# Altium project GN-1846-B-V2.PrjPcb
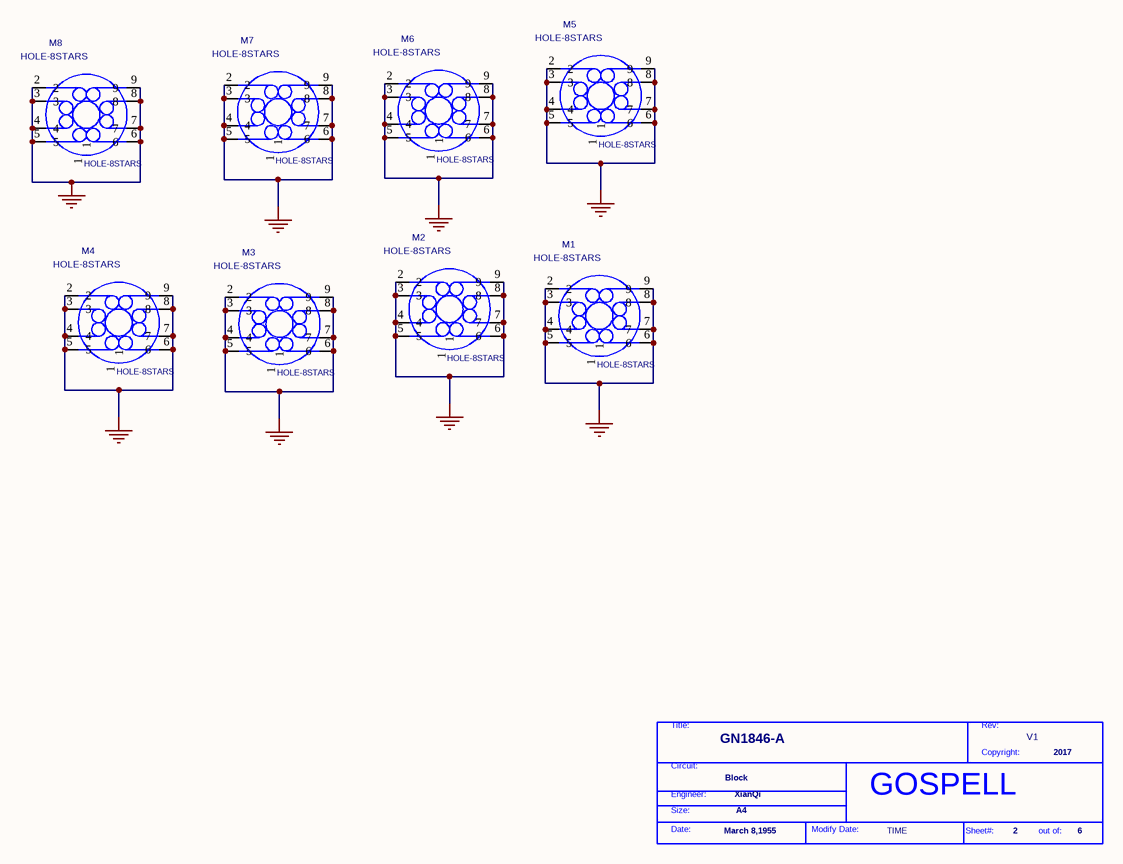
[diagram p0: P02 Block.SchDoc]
6 sheets, 362 parts. Net scope: flat (ports and power ports of the same name join across sheets).
Board file: GN-1846-B-V2.PcbDoc
Sheets:
  P02 Block.SchDoc
  P05 PHY 3.SchDoc
  P06 CONNECT & LED.SchDoc
  P04 PHY 2.SchDoc
  P03 PHY 1.SchDoc
  P01 Note & Title.SchDoc

## Sheet P02 Block.SchDoc
size 297 x 209 mm

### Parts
(Parts that share a designator on the sheet are numbered #1, #2 ... from top to bottom, then left to right.)
*#1  Page Modify Date: TIME  Engineer: XianQi  Copyright: 2017  Title: GN1846-A  RevCode: V1  Page Size: A4  Page Create Date: March 8,1955  Page Number: 2  Page Count: 6  Doc: Block  (hidden comment: GOSPELL)  (graphical)
M1  HOLE-8STARS  [HK]
M2  HOLE-8STARS  [HK]
M3  HOLE-8STARS  [HK]
M4  HOLE-8STARS  [HK]
M5  HOLE-8STARS  [HK]
M6  HOLE-8STARS  [HK]
M7  HOLE-8STARS  [HK]
M8  HOLE-8STARS  [HK]

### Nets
GND: M1.2 M1.3 M1.4 M1.5 M1.6 M1.7 M1.8 M1.9 M2.2 M2.3 M2.4 M2.5 M2.6 M2.7 M2.8 M2.9 M3.2 M3.3 M3.4 M3.5 M3.6 M3.7 M3.8 M3.9 M4.2 M4.3 M4.4 M4.5 M4.6 M4.7 M4.8 M4.9 M5.2 M5.3 M5.4 M5.5 M5.6 M5.7 M5.8 M5.9 M6.2 M6.3 M6.4 M6.5 M6.6 M6.7 M6.8 M6.9 M7.2 M7.3 M7.4 M7.5 M7.6 M7.7 M7.8 M7.9 M8.2 M8.3 M8.4 M8.5 M8.6 M8.7 M8.8 M8.9

Not connected (* = marked no-connect by the designer): M1 1; M2 1; M3 1; M4 1; M5 1; M6 1; M7 1; M8 1

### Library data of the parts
M1-M8 = GEN35: Layer: Top

## Sheet P05 PHY 3.SchDoc
size 420 x 297 mm
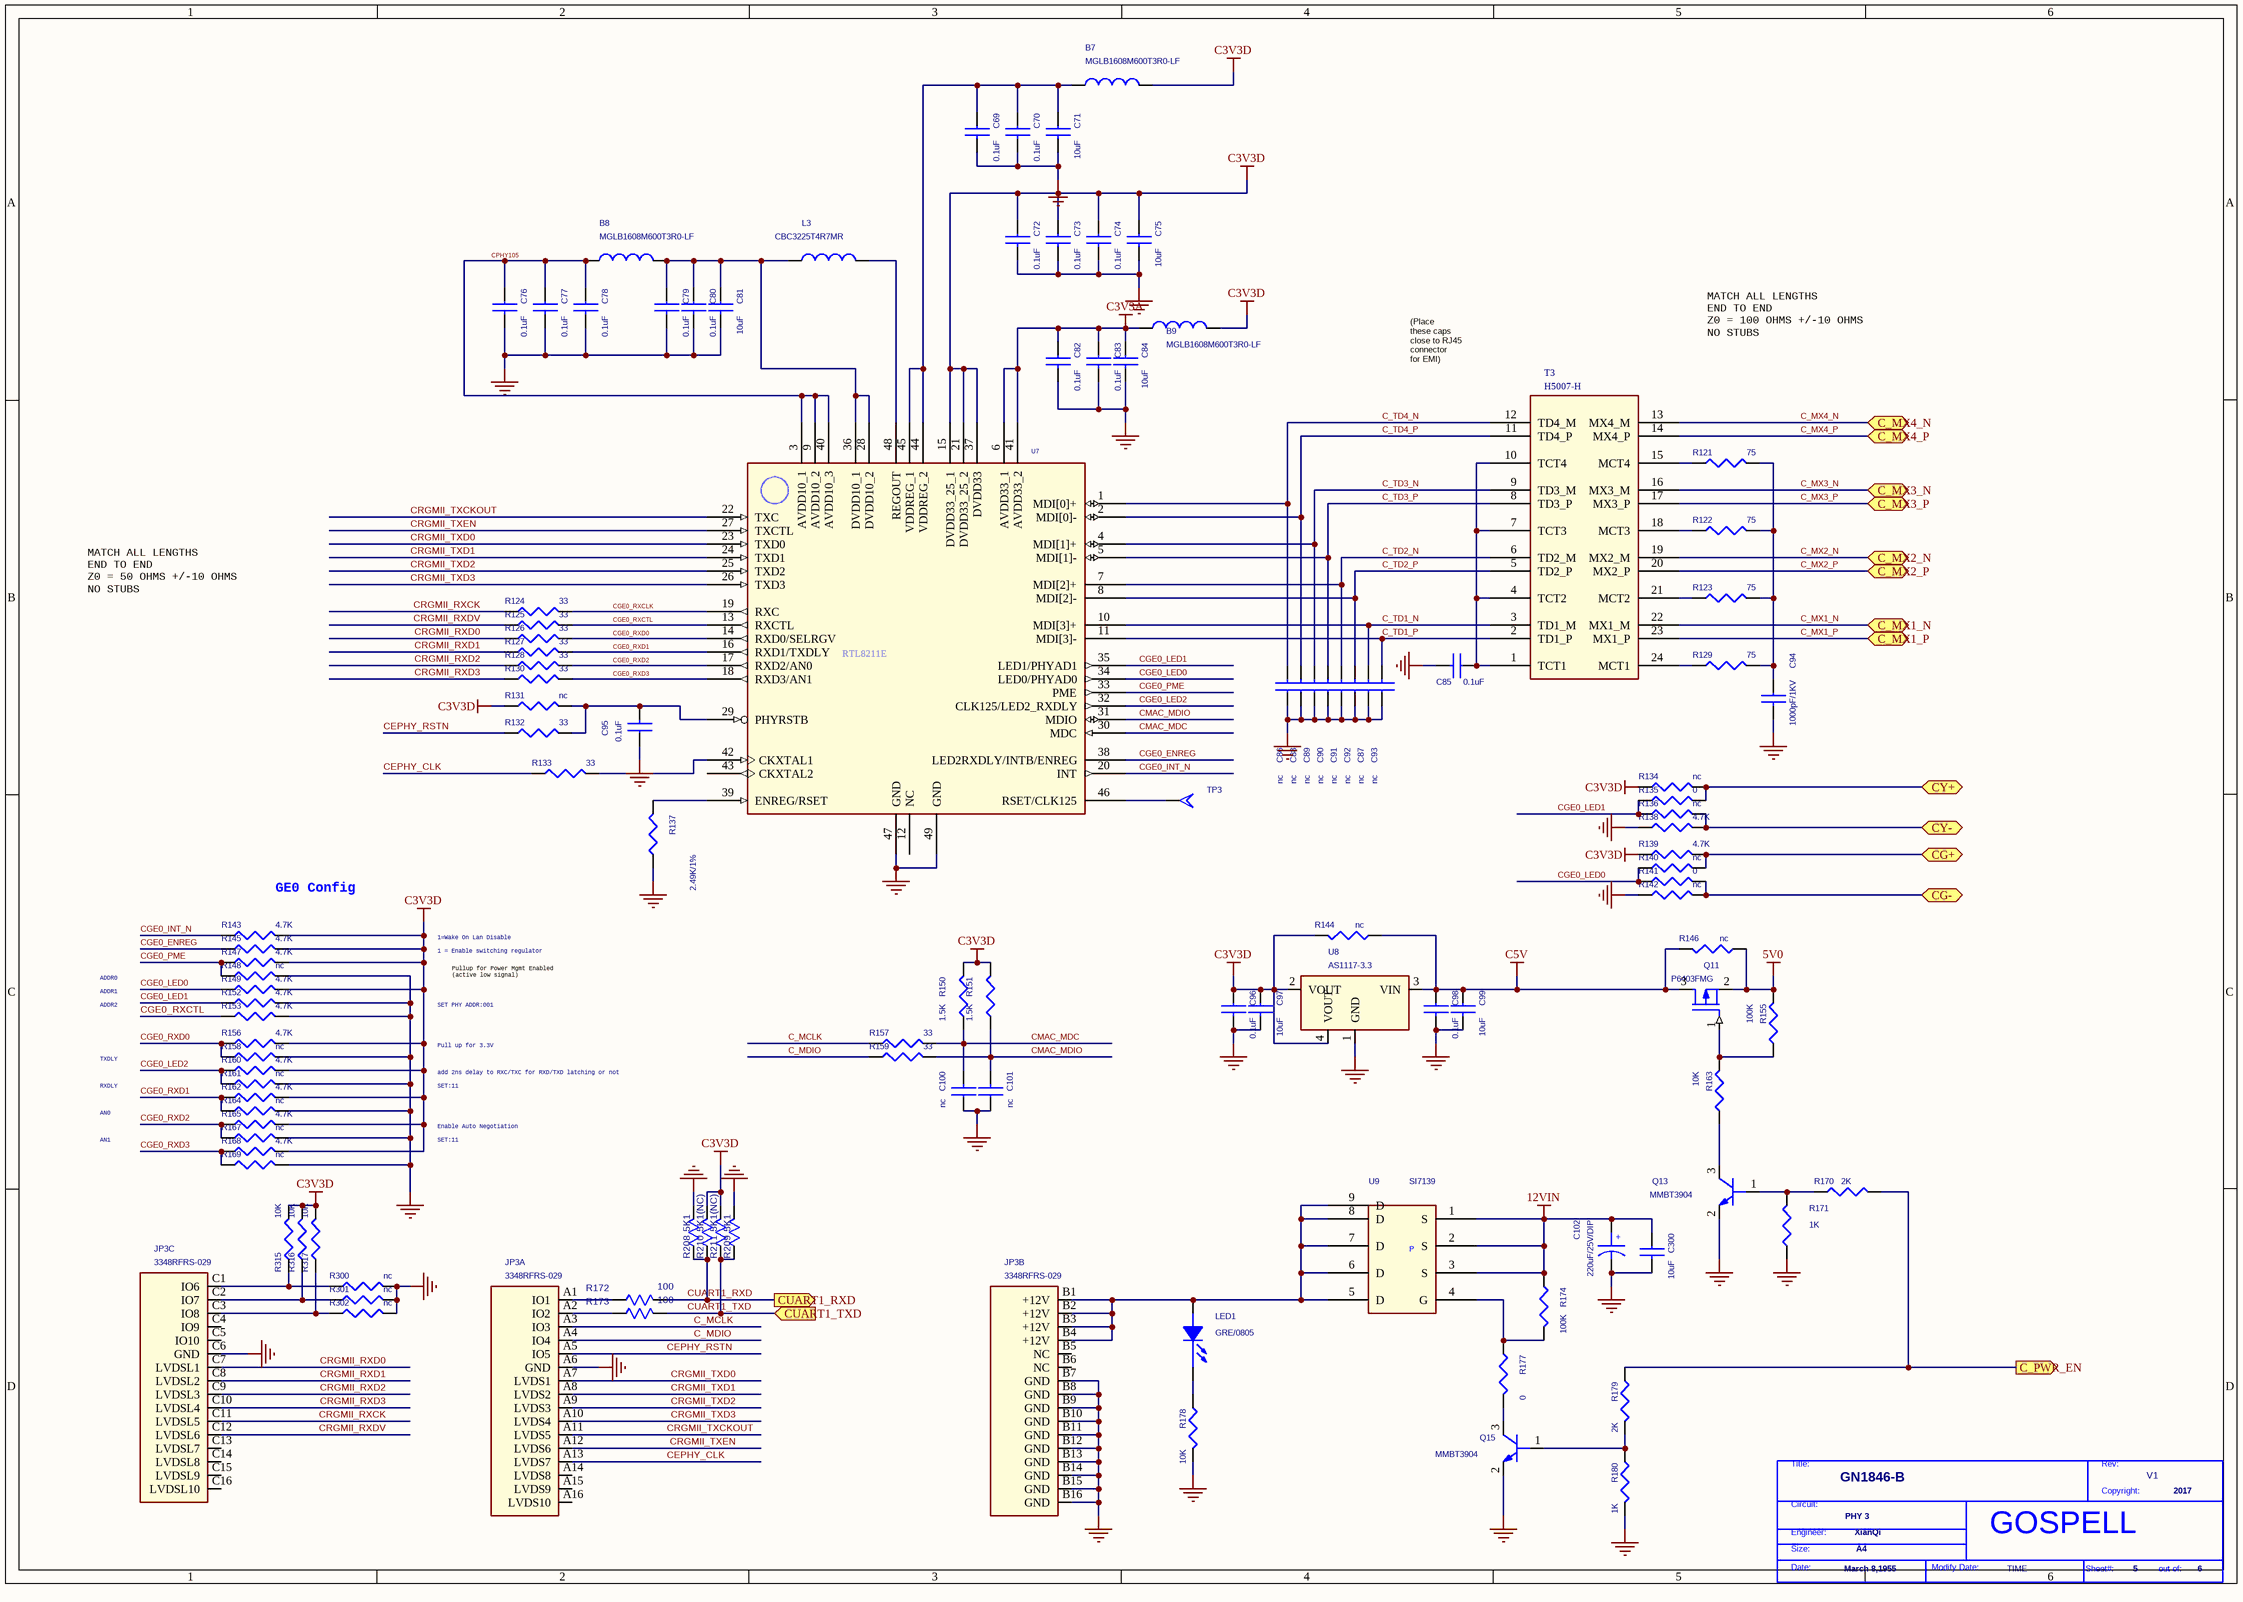
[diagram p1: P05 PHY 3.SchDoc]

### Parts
(Parts that share a designator on the sheet are numbered #1, #2 ... from top to bottom, then left to right.)
*#2  Page Modify Date: TIME  Engineer: XianQi  Copyright: 2017  Title: GN1846-B  RevCode: V1  Page Size: A4  Page Create Date: March 8,1955  Page Number: 5  Page Count: 6  Doc: PHY 3  (hidden comment: GOSPELL)  (graphical)
B7  MGLB1608M600T3R0-LF  [L0603]
B8  MGLB1608M600T3R0-LF  [L0603]
B9  MGLB1608M600T3R0-LF  [L0603]
C69  0.1uF  [0402C]
C70  0.1uF  [0402C]
C71  10uF  [C0603]
C72  0.1uF  [0402C]
C73  0.1uF  [0402C]
C74  0.1uF  [0402C]
C75  10uF  [C0603]
C76  0.1uF  [0402C]
C77  0.1uF  [0402C]
C78  0.1uF  [0402C]
C79  0.1uF  [0402C]
C80  0.1uF  [0402C]
C81  10uF  [C0603]
C82  0.1uF  [0402C]
C83  0.1uF  [0402C]
C84  10uF  [C0603]
C85  0.1uF  [0402C]
C86  nc  [0402C]
C87  nc  [0402C]
C88  nc  [0402C]
C89  nc  [0402C]
C90  nc  [0402C]
C91  nc  [0402C]
C92  nc  [0402C]
C93  nc  [0402C]
C94  1000pF/1KV  [C1206]
C95  0.1uF  [0402C]
C96  0.1uF  [0402C]
C97  10uF  [C0603]
C98  0.1uF  [0402C]
C99  10uF  [C0603]
C100  nc  [0402C]
C101  nc  [0402C]
C102  220uF/25V/DIP  [CE8X3.5]
C300  10uF  [c1206]
JP3  3348RFRS-029  [3348RFRS-029]  (parts A,B,C of 3)
L3  CBC3225T4R7MR  [FB0805]
LED1  GRE/0805  [LED0805]
Q11  P6403FMG  [SOT23]
Q13  MMBT3904  [SOT23]
Q15  MMBT3904  [SOT23]
R121  75  [0402R]
R122  75  [0402R]
R123  75  [0402R]
R124  33  [0402R]
R125  33  [0402R]
R126  33  [0402R]
R127  33  [0402R]
R128  33  [0402R]
R129  75  [0402R]
R130  33  [0402R]
R131  nc  [0402R]
R132  33  [0402R]
R133  33  [0402R]
R134  nc  [0402R]
R135  0  [0402R]
R136  nc  [0402R]
R137  2.49K/1%  [0402R]
R138  4.7K  [0402R]
R139  4.7K  [0402R]
R140  nc  [0402R]
R141  0  [0402R]
R142  nc  [0402R]
R143  4.7K  [0402R]
R144  nc  [R0603]
R145  4.7K  [0402R]
R146  nc  [R0603]
R147  4.7K  [0402R]
R148  nc  [0402R]
R149  4.7K  [0402R]
R150  1.5K  [0402R]
R151  1.5K  [0402R]
R152  4.7K  [0402R]
R153  4.7K  [0402R]
R155  100K  [R0603]
R156  4.7K  [0402R]
R157  33  [0402R]
R158  nc  [0402R]
R159  33  [0402R]
R160  4.7K  [0402R]
R161  nc  [0402R]
R162  4.7K  [0402R]
R163  10K  [0402R]
R164  nc  [0402R]
R165  4.7K  [0402R]
R167  nc  [0402R]
R168  4.7K  [0402R]
R169  nc  [0402R]
R170  2K  [0402R]
R171  1K  [0402R]
R172  100  [0402R]
R173  100  [0402R]
R174  100K  [R0603]
R177  0  [0402R]
R178  10K  [0402R]
R179  2K  [0402R]
R180  1K  [0402R]
R208  5K1  [0402R]
R209  5K1  [0402R]
R210  5K1(NC)  [0402R]
R211  5K1(NC)  [0402R]
R300  nc  [0402R]
R301  nc  [0402R]
R302  nc  [0402R]
R315  10K  [0402R]
R316  10K  [0402R]
R317  10K  [0402R]
T3  H5007-H  [H5007-H]
TP3  T POINT A  [TP_G]  (value not drawn)
U7  RTL8211D  [QFN-48P-RTL8211]  (value not drawn)
U8  AS1117-3.3  [SOT223]
U9  SI7139  [PowerPAKSO8]

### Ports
C_MX1_N (bidir), C_MX1_P (bidir), C_MX2_N (bidir), C_MX2_P (bidir), C_MX3_N (bidir), C_MX3_P (bidir), C_MX4_N (bidir), C_MX4_P (bidir), C_PWR_EN (out), CG+ (bidir), CG- (bidir), CUART1_RXD (out), CUART1_TXD (in), CY+ (bidir), CY- (bidir)

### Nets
5V0: Q11.2(SOURCE) R146.2 R155.1
12VIN: C102.1 C300.1 R174.2 U9.1(S) U9.2(S) U9.3(S)
C3V3A: B9.1 C82.1 C83.1 C84.1 U7.6(AVDD33_1) U7.41(AVDD33_2)
C3V3D: B7.2 B9.2 C72.1 C73.1 C74.1 C75.1 C96.1 C97.1 R131.1 R134.1 R139.1 R143.2 R144.1 R145.2 R147.2 R149.2 R150.2 R151.2 R156.2 R160.2 R162.2 R165.2 R168.2 R210.2(B) R211.2(B) R315.2 R316.2 R317.2 U7.15(DVDD33_25_1) U7.21(DVDD33_25_2) U7.37(DVDD33) U8.2(VOUT) U8.4(VOUT)
C5V: C98.1 C99.1 Q11.3(DRAIN) R144.2 R146.1 U8.3(VIN)
GND: C69.2 C70.2 C71.2 C72.2 C73.2 C74.2 C75.2 C76.2 C77.2 C78.2 C79.2 C80.2 C81.2 C82.2 C83.2 C84.2 C85.2 C86.1 C87.1 C88.1 C89.1 C90.1 C91.1 C92.1 C93.1 C94.2 C95.1 C96.2 C97.2 C98.2 C99.2 C100.1 C101.1 C102.2 C300.2 JP3.A6(GND) JP3.B7(GND) JP3.B8(GND) JP3.B9(GND) JP3.B10(GND) JP3.B11(GND) JP3.B12(GND) JP3.B13(GND) JP3.B14(GND) JP3.B15(GND) JP3.B16(GND) JP3.C6(GND) Q13.2(EMITTER) Q15.2(EMITTER) R137.1 R138.1 R142.1 R148.2 R152.2 R153.2 R158.2 R161.2 R164.2 R167.2 R169.2 R171.1 R178.1 R180.1 R208.2(B) R209.2(B) R300.2 R301.2 R302.2 U7.47(GND) U7.49(GND) U8.1(GND)
C_MCLK: JP3.A3(IO3) R157.1
C_MDIO: JP3.A4(IO4) R159.1
C_MX1_N: T3.22(MX1_M) ; port C_MX1_N
C_MX1_P: T3.23(MX1_P) ; port C_MX1_P
C_MX2_N: T3.19(MX2_M) ; port C_MX2_N
C_MX2_P: T3.20(MX2_P) ; port C_MX2_P
C_MX3_N: T3.16(MX3_M) ; port C_MX3_N
C_MX3_P: T3.17(MX3_P) ; port C_MX3_P
C_MX4_N: T3.13(MX4_M) ; port C_MX4_N
C_MX4_P: T3.14(MX4_P) ; port C_MX4_P
C_TD1_N: C87.2 T3.3(TD1_M) U7.10(MDI[3]+)
C_TD1_P: C93.2 T3.2(TD1_P) U7.11(MDI[3]-)
C_TD2_N: C91.2 T3.6(TD2_M) U7.7(MDI[2]+)
C_TD2_P: C92.2 T3.5(TD2_P) U7.8(MDI[2]-)
C_TD3_N: C89.2 T3.9(TD3_M) U7.4(MDI[1]+)
C_TD3_P: C90.2 T3.8(TD3_P) U7.5(MDI[1]-)
C_TD4_N: C86.2 T3.12(TD4_M) U7.1(MDI[0]+)
C_TD4_P: C88.2 T3.11(TD4_P) U7.2(MDI[0]-)
CEPHY_CLK: JP3.A13(LVDS7) R133.1
CEPHY_RSTN: JP3.A5(IO5) R132.1
CGE0_ENREG: R145.1 U7.38(LED2RXDLY/INTB/ENREG)
CGE0_INT_N: R143.1 U7.20(INT)
CGE0_LED0: R140.1 R141.1 R149.1 U7.34(LED0/PHYAD0)
CGE0_LED1: R135.1 R136.1 R152.1 U7.35(LED1/PHYAD1)
CGE0_LED2: R160.1 R161.1 U7.32(CLK125/LED2_RXDLY)
CGE0_PME: R147.1 R148.1 U7.33(PME)
CGE0_RXCLK: R124.2 U7.19(RXC)
CGE0_RXCTL: R125.2 R153.1 U7.13(RXCTL)
CGE0_RXD0: R126.2 R156.1 R158.1 U7.14(RXD0/SELRGV)
CGE0_RXD1: R127.2 R162.1 R164.1 U7.16(RXD1/TXDLY)
CGE0_RXD2: R128.2 R165.1 R167.1 U7.17(RXD2/AN0)
CGE0_RXD3: R130.2 R168.1 R169.1 U7.18(RXD3/AN1)
CMAC_MDC: C100.2 R150.1 R157.2 U7.30(MDC)
CMAC_MDIO: C101.2 R151.1 R159.2 U7.31(MDIO)
CPHY105: B8.1 C76.1 C77.1 C78.1 U7.3(AVDD10_1) U7.9(AVDD10_2) U7.40(AVDD10_3)
CRGMII_RXCK: JP3.C11(LVDSL5) R124.1
CRGMII_RXD0: JP3.C7(LVDSL1) R126.1
CRGMII_RXD1: JP3.C8(LVDSL2) R127.1
CRGMII_RXD2: JP3.C9(LVDSL3) R128.1
CRGMII_RXD3: JP3.C10(LVDSL4) R130.1
CRGMII_RXDV: JP3.C12(LVDSL6) R125.1
CRGMII_TXCKOUT: JP3.A11(LVDS5) U7.22(TXC)
CRGMII_TXD0: JP3.A7(LVDS1) U7.23(TXD0)
CRGMII_TXD1: JP3.A8(LVDS2) U7.24(TXD1)
CRGMII_TXD2: JP3.A9(LVDS3) U7.25(TXD2)
CRGMII_TXD3: JP3.A10(LVDS4) U7.26(TXD3)
CRGMII_TXEN: JP3.A12(LVDS6) U7.27(TXCTL)
CUART1_RXD: R172.2(B) R208.1(A) R210.1(A) ; port CUART1_RXD
CUART1_TXD: R173.2(B) R209.1(A) R211.1(A) ; port CUART1_TXD
NetB7_1: B7.1 C69.1 C70.1 C71.1 U7.44(VDDREG_2) U7.45(VDDREG_1)
NetB8_2: B8.2 C79.1 C80.1 C81.1 L3.1 U7.28(DVDD10_2) U7.36(DVDD10_1)
NetC85_1: C85.1 T3.1(TCT1) T3.4(TCT2) T3.7(TCT3) T3.10(TCT4)
NetC94_1: C94.1 R121.2 R122.2 R123.2 R129.2
NetC95_2: C95.2 R131.2 R132.2 U7.29(PHYRSTB)
NetJ3_18: R170.2 R179.2 ; port C_PWR_EN
NetJ4_15: R134.2 R135.2 ; port CY+
NetJ4_16: R136.2 R138.2 ; port CY-
NetJ4_17: R139.2 R140.2 ; port CG+
NetJ4_18: R141.2 R142.2 ; port CG-
NetJP3_A1: JP3.A1(IO1) R172.1(A)
NetJP3_A2: JP3.A2(IO2) R173.1(A)
NetJP3_B1: JP3.B1(+12V) JP3.B2(+12V) JP3.B3(+12V) JP3.B4(+12V) LED1.A(ANODE) U9.5(D) U9.6(D) U9.7(D) U9.8(D) U9.9(D)
NetJP3_C1: JP3.C1(IO6) R300.1 R315.1
NetJP3_C2: JP3.C2(IO7) R301.1 R316.1
NetJP3_C3: JP3.C3(IO8) R302.1 R317.1
NetL3_2: L3.2 U7.48(REGOUT)
NetLED1_K: LED1.K(CATHODE) R178.2
NetQ11_1: Q11.1(GATE) R155.2 R163.1
NetQ13_1: Q13.1(BASE) R170.1 R171.2
NetQ13_3: Q13.3(COLLECTOR) R163.2
NetQ15_1: Q15.1(BASE) R179.1 R180.2
NetQ15_3: Q15.3(COLLECTOR) R177.1
NetR121_1: R121.1 T3.15(MCT4)
NetR122_1: R122.1 T3.18(MCT3)
NetR123_1: R123.1 T3.21(MCT2)
NetR129_1: R129.1 T3.24(MCT1)
NetR133_2: R133.2 U7.42(CKXTAL1)
NetR137_2: R137.2 U7.39(ENREG/RSET)
NetR174_1: R174.1 R177.2 U9.4(G)
NetTP3_1: TP3.1(TP) U7.46(RSET/CLK125)

Not connected (* = marked no-connect by the designer): JP3 A14(LVDS8) A15(LVDS9) A16(LVDS10) B5(NC) B6(NC) C4(IO9) C5(IO10) C13(LVDSL7) C14(LVDSL8) C15(LVDSL9) C16(LVDSL10); U7 12(NC) 43(CKXTAL2)

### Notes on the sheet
- (Place
  these caps
  close to RJ45
  connector
  for EMI)
- MATCH ALL LENGTHS
  END TO END
  Z0 = 100 OHMS +/-10 OHMS
  NO STUBS
- MATCH ALL LENGTHS
  END TO END
  Z0 = 50 OHMS +/-10 OHMS
  NO STUBS
- GE0 Config
- 1=Wake On Lan Disable
- ADDR0
- ADDR1
- 1 = Enable switching regulator
- Pullup for Power Mgmt Enabled
  (active low signal)
- ADDR2
- TXDLY
- SET PHY ADDR:001
- Pull up for 3.3V
- add 2ns delay to RXC/TXC for RXD/TXD latching or not
- AN0
- RXDLY
- Enable Auto Negotiation
- SET:11
- AN1

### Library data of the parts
B7-B9 L3 = CHOKE TORROID_0
C69-C101 C300 = CAP NP
C102 = CAP POL
LED1 = LED_2
Q11 = MOSFET P_0
Q13 Q15 = 2N3904
R121-R143 R145 R147-R153 R156-R162 R164 R165 R167-R169 R174 R177 R179 R180 R300-R302 R315-R317 = R_0
R144 R146 R155 R163 R170 R171 = R
R172 R173 R208-R211 = R_1_Dup1: PARTS: 1; LEVEL: STD; PKG_TYPE: SR0603; DEVICE: RK73H1JTTD7502F; PINSWAP: (A,B); OriginalSymbolOrigin: (10,20); CODE: 7091238; %195%%232%%202%%246%: 片式厚膜电阻器-0.1W-75000OHM-+/-1%-0603; %182%%238%%182%%168%%185%%166%%194%%202%(W): 0.1; %215%%232%%214%%181%%212%%202%%208%%237%%198%%171%%178%%238%: +/-1%; COMPONENT_HIGH_MAX: 0.55MM; %208%%161%%192%%224%%195%%251%%179%%198%: 片式厚膜电阻器
R178 = R_1
T3 = PULSE H5007_0
U7 = RTL8211D_0
U8 = AS1117-X_1

## Sheet P06 CONNECT & LED.SchDoc
size 297 x 209 mm
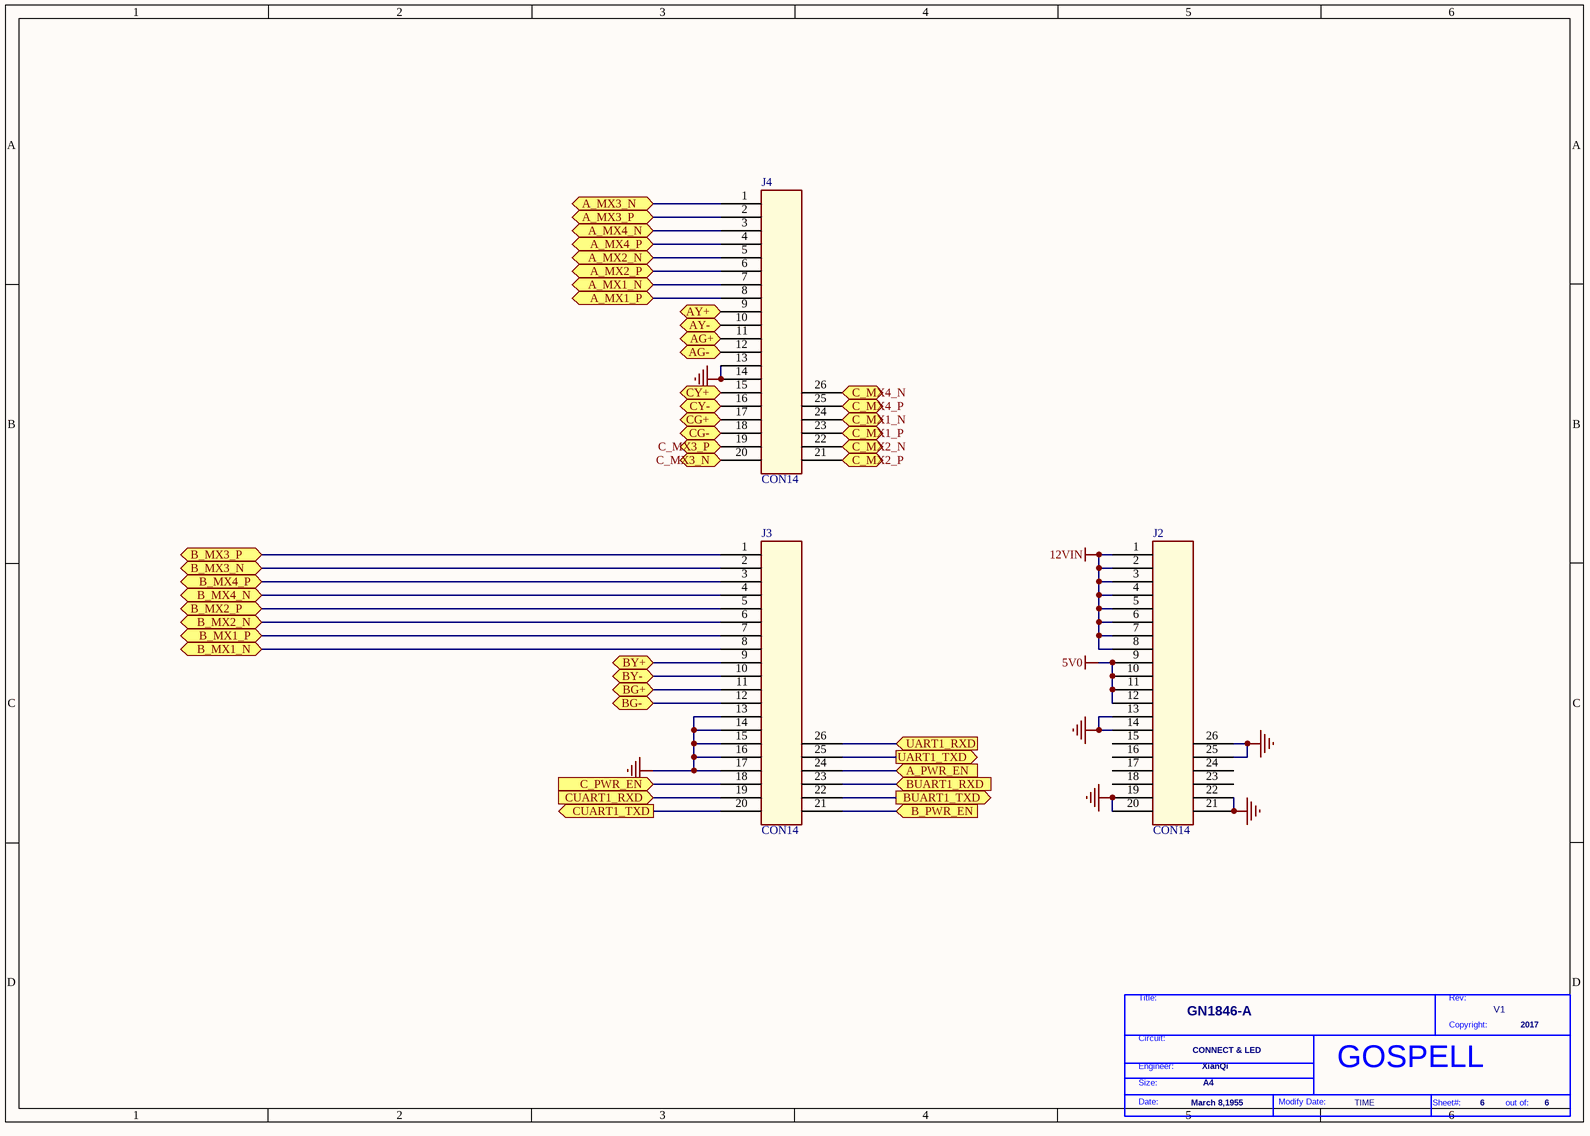
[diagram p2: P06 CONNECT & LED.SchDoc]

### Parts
(Parts that share a designator on the sheet are numbered #1, #2 ... from top to bottom, then left to right.)
*#3  Page Modify Date: TIME  Engineer: XianQi  Copyright: 2017  Title: GN1846-A  RevCode: V1  Page Size: A4  Page Create Date: March 8,1955  Page Number: 6  Doc: CONNECT & LED  (hidden comment: GOSPELL)  (graphical)
J2  CON14  [HERDER13X2-2.0]
J3  CON14  [HERDER13X2-2.0]
J4  CON14  [HERDER13X2-2.0]

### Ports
A_MX1_N (bidir), A_MX1_P (bidir), A_MX2_N (bidir), A_MX2_P (bidir), A_MX3_N (bidir), A_MX3_P (bidir), A_MX4_N (bidir), A_MX4_P (bidir), A_PWR_EN (in), AG+ (bidir), AG- (bidir), AY+ (bidir), AY- (bidir), B_MX1_N (bidir), B_MX1_P (bidir), B_MX2_N (bidir), B_MX2_P (bidir), B_MX3_N (bidir), B_MX3_P (bidir), B_MX4_N (bidir), B_MX4_P (bidir), B_PWR_EN (in), BG+ (bidir), BG- (bidir), BUART1_RXD (in), BUART1_TXD (out), BY+ (bidir), BY- (bidir), C_MX1_N (bidir), C_MX1_P (bidir), C_MX2_N (bidir), C_MX2_P (bidir), C_MX3_N (bidir), C_MX3_P (bidir), C_MX4_N (bidir), C_MX4_P (bidir), C_PWR_EN (in), CG+ (bidir), CG- (bidir), CUART1_RXD (in), CUART1_TXD (out), CY+ (bidir), CY- (bidir), UART1_RXD (in), UART1_TXD (out)

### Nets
5V0: J2.9 J2.10 J2.11 J2.12
12VIN: J2.1 J2.2 J2.3 J2.4 J2.5 J2.6 J2.7 J2.8
GND: J2.13 J2.14 J2.19 J2.20 J2.21 J2.22 J2.25 J2.26 J3.13 J3.14 J3.15 J3.16 J3.17 J4.13 J4.14
A_MX1_N: J4.7 ; port A_MX1_N
A_MX1_P: J4.8 ; port A_MX1_P
A_MX2_N: J4.5 ; port A_MX2_N
A_MX2_P: J4.6 ; port A_MX2_P
A_MX3_N: J4.1 ; port A_MX3_N
A_MX3_P: J4.2 ; port A_MX3_P
A_MX4_N: J4.3 ; port A_MX4_N
A_MX4_P: J4.4 ; port A_MX4_P
B_MX1_N: J3.8 ; port B_MX1_N
B_MX1_P: J3.7 ; port B_MX1_P
B_MX2_N: J3.6 ; port B_MX2_N
B_MX2_P: J3.5 ; port B_MX2_P
B_MX3_N: J3.2 ; port B_MX3_N
B_MX3_P: J3.1 ; port B_MX3_P
B_MX4_N: J3.4 ; port B_MX4_N
B_MX4_P: J3.3 ; port B_MX4_P
BUART1_RXD: J3.23 ; port BUART1_RXD
BUART1_TXD: J3.22 ; port BUART1_TXD
C_MX1_N: J4.24 ; port C_MX1_N
C_MX1_P: J4.23 ; port C_MX1_P
C_MX2_N: J4.22 ; port C_MX2_N
C_MX2_P: J4.21 ; port C_MX2_P
C_MX3_N: J4.20 ; port C_MX3_N
C_MX3_P: J4.19 ; port C_MX3_P
C_MX4_N: J4.26 ; port C_MX4_N
C_MX4_P: J4.25 ; port C_MX4_P
CUART1_RXD: J3.19 ; port CUART1_RXD
CUART1_TXD: J3.20 ; port CUART1_TXD
UART1_RXD: J3.26 ; port UART1_RXD
UART1_TXD: J3.25 ; port UART1_TXD
NetJ3_9: J3.9 ; port BY+
NetJ3_10: J3.10 ; port BY-
NetJ3_11: J3.11 ; port BG+
NetJ3_12: J3.12 ; port BG-
NetJ3_18: J3.18 ; port C_PWR_EN
NetJ3_21: J3.21 ; port B_PWR_EN
NetJ3_24: J3.24 ; port A_PWR_EN
NetJ4_9: J4.9 ; port AY+
NetJ4_10: J4.10 ; port AY-
NetJ4_11: J4.11 ; port AG+
NetJ4_12: J4.12 ; port AG-
NetJ4_15: J4.15 ; port CY+
NetJ4_16: J4.16 ; port CY-
NetJ4_17: J4.17 ; port CG+
NetJ4_18: J4.18 ; port CG-

Not connected (* = marked no-connect by the designer): J2 15(14) 16(14) 17(14) 18(14) 23(14) 24(14)

## Sheet P04 PHY 2.SchDoc
size 420 x 297 mm
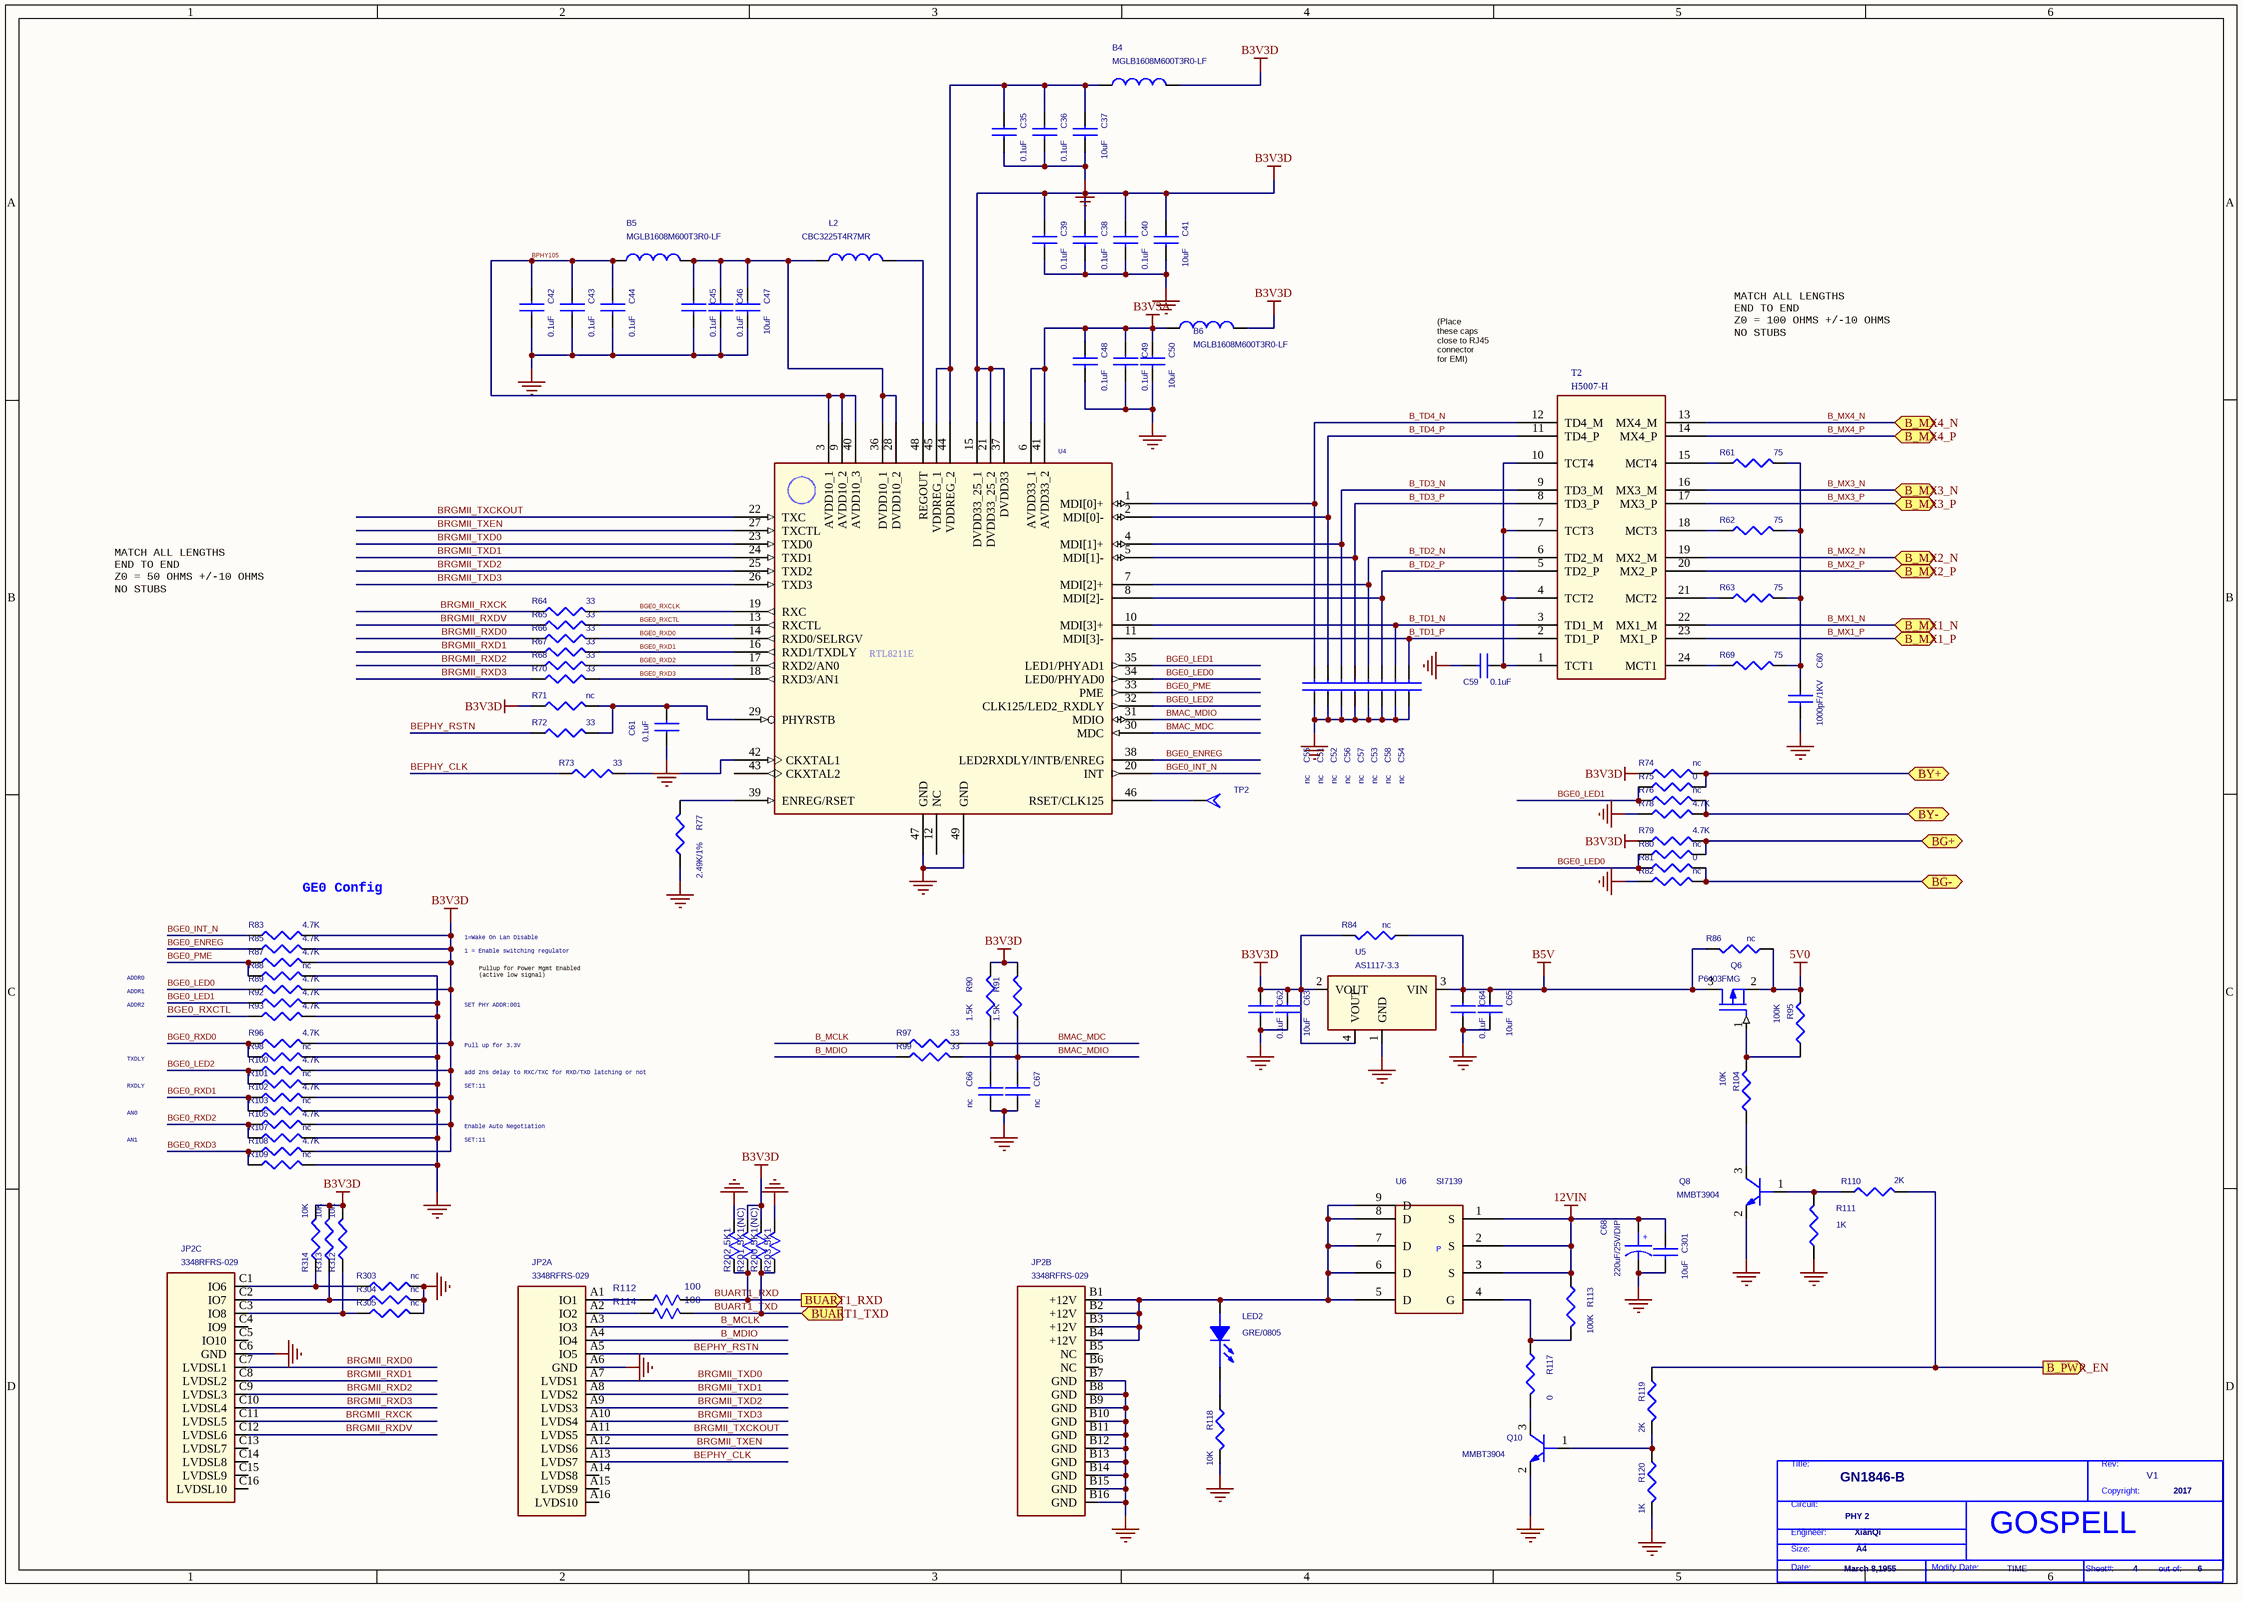
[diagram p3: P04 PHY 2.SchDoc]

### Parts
(Parts that share a designator on the sheet are numbered #1, #2 ... from top to bottom, then left to right.)
*#4  Page Modify Date: TIME  Engineer: XianQi  Copyright: 2017  Title: GN1846-B  RevCode: V1  Page Size: A4  Page Create Date: March 8,1955  Page Number: 4  Page Count: 6  Doc: PHY 2  (hidden comment: GOSPELL)  (graphical)
B4  MGLB1608M600T3R0-LF  [L0603]
B5  MGLB1608M600T3R0-LF  [L0603]
B6  MGLB1608M600T3R0-LF  [L0603]
C35  0.1uF  [0402C]
C36  0.1uF  [0402C]
C37  10uF  [C0603]
C38  0.1uF  [0402C]
C39  0.1uF  [0402C]
C40  0.1uF  [0402C]
C41  10uF  [C0603]
C42  0.1uF  [0402C]
C43  0.1uF  [0402C]
C44  0.1uF  [0402C]
C45  0.1uF  [0402C]
C46  0.1uF  [0402C]
C47  10uF  [C0603]
C48  0.1uF  [0402C]
C49  0.1uF  [0402C]
C50  10uF  [C0603]
C51  nc  [0402C]
C52  nc  [0402C]
C53  nc  [0402C]
C54  nc  [0402C]
C55  nc  [0402C]
C56  nc  [0402C]
C57  nc  [0402C]
C58  nc  [0402C]
C59  0.1uF  [0402C]
C60  1000pF/1KV  [C1206]
C61  0.1uF  [0402C]
C62  0.1uF  [0402C]
C63  10uF  [C0603]
C64  0.1uF  [0402C]
C65  10uF  [C0603]
C66  nc  [0402C]
C67  nc  [0402C]
C68  220uF/25V/DIP  [CE8X3.5]
C301  10uF  [c1206]
JP2  3348RFRS-029  [3348RFRS-029]  (parts A,B,C of 3)
L2  CBC3225T4R7MR  [FB0805]
LED2  GRE/0805  [LED0805]
Q6  P6403FMG  [SOT23]
Q8  MMBT3904  [SOT23]
Q10  MMBT3904  [SOT23]
R61  75  [0402R]
R62  75  [0402R]
R63  75  [0402R]
R64  33  [0402R]
R65  33  [0402R]
R66  33  [0402R]
R67  33  [0402R]
R68  33  [0402R]
R69  75  [0402R]
R70  33  [0402R]
R71  nc  [0402R]
R72  33  [0402R]
R73  33  [0402R]
R74  nc  [0402R]
R75  0  [0402R]
R76  nc  [0402R]
R77  2.49K/1%  [0402R]
R78  4.7K  [0402R]
R79  4.7K  [0402R]
R80  nc  [0402R]
R81  0  [0402R]
R82  nc  [0402R]
R83  4.7K  [0402R]
R84  nc  [R0603]
R85  4.7K  [0402R]
R86  nc  [R0603]
R87  4.7K  [0402R]
R88  nc  [0402R]
R89  4.7K  [0402R]
R90  1.5K  [0402R]
R91  1.5K  [0402R]
R92  4.7K  [0402R]
R93  4.7K  [0402R]
R95  100K  [0402R]
R96  4.7K  [0402R]
R97  33  [0402R]
R98  nc  [0402R]
R99  33  [0402R]
R100  4.7K  [0402R]
R101  nc  [0402R]
R102  4.7K  [0402R]
R103  nc  [0402R]
R104  10K  [0402R]
R105  4.7K  [0402R]
R107  nc  [0402R]
R108  4.7K  [0402R]
R109  nc  [0402R]
R110  2K  [0402R]
R111  1K  [0402R]
R112  100  [0402R]
R113  100K  [R0603]
R114  100  [0402R]
R117  0  [0402R]
R118  10K  [0402R]
R119  2K  [0402R]
R120  1K  [0402R]
R200  5K1(NC)  [0402R]
R201  5K1(NC)  [0402R]
R202  5K1  [0402R]
R203  5K1  [0402R]
R303  nc  [0402R]
R304  nc  [0402R]
R305  nc  [0402R]
R312  10K  [0402R]
R313  10K  [0402R]
R314  10K  [0402R]
T2  H5007-H  [H5007-H]
TP2  T POINT A  [TP_G]  (value not drawn)
U4  RTL8211D  [QFN-48P-RTL8211]  (value not drawn)
U5  AS1117-3.3  [SOT223]
U6  SI7139  [PowerPAKSO8]

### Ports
B_MX1_N (bidir), B_MX1_P (bidir), B_MX2_N (bidir), B_MX2_P (bidir), B_MX3_N (bidir), B_MX3_P (bidir), B_MX4_N (bidir), B_MX4_P (bidir), B_PWR_EN (out), BG+ (bidir), BG- (bidir), BUART1_RXD (out), BUART1_TXD (in), BY+ (bidir), BY- (bidir)

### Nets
5V0: Q6.2(SOURCE) R86.2 R95.1
12VIN: C68.1 C301.1 R113.2 U6.1(S) U6.2(S) U6.3(S)
B3V3A: B6.1 C48.1 C49.1 C50.1 U4.6(AVDD33_1) U4.41(AVDD33_2)
B3V3D: B4.2 B6.2 C38.1 C39.1 C40.1 C41.1 C62.1 C63.1 R71.1 R74.1 R79.1 R83.2 R84.1 R85.2 R87.2 R89.2 R90.2 R91.2 R96.2 R100.2 R102.2 R105.2 R108.2 R200.2(B) R201.2(B) R312.2 R313.2 R314.2 U4.15(DVDD33_25_1) U4.21(DVDD33_25_2) U4.37(DVDD33) U5.2(VOUT) U5.4(VOUT)
B5V: C64.1 C65.1 Q6.3(DRAIN) R84.2 R86.1 U5.3(VIN)
GND: C35.2 C36.2 C37.2 C38.2 C39.2 C40.2 C41.2 C42.2 C43.2 C44.2 C45.2 C46.2 C47.2 C48.2 C49.2 C50.2 C51.1 C52.1 C53.1 C54.1 C55.1 C56.1 C57.1 C58.1 C59.2 C60.2 C61.1 C62.2 C63.2 C64.2 C65.2 C66.1 C67.1 C68.2 C301.2 JP2.A6(GND) JP2.B7(GND) JP2.B8(GND) JP2.B9(GND) JP2.B10(GND) JP2.B11(GND) JP2.B12(GND) JP2.B13(GND) JP2.B14(GND) JP2.B15(GND) JP2.B16(GND) JP2.C6(GND) Q8.2(EMITTER) Q10.2(EMITTER) R77.1 R78.1 R82.1 R88.2 R92.2 R93.2 R98.2 R101.2 R103.2 R107.2 R109.2 R111.1 R118.1 R120.1 R202.2(B) R203.2(B) R303.2 R304.2 R305.2 U4.47(GND) U4.49(GND) U5.1(GND)
B_MCLK: JP2.A3(IO3) R97.1
B_MDIO: JP2.A4(IO4) R99.1
B_MX1_N: T2.22(MX1_M) ; port B_MX1_N
B_MX1_P: T2.23(MX1_P) ; port B_MX1_P
B_MX2_N: T2.19(MX2_M) ; port B_MX2_N
B_MX2_P: T2.20(MX2_P) ; port B_MX2_P
B_MX3_N: T2.16(MX3_M) ; port B_MX3_N
B_MX3_P: T2.17(MX3_P) ; port B_MX3_P
B_MX4_N: T2.13(MX4_M) ; port B_MX4_N
B_MX4_P: T2.14(MX4_P) ; port B_MX4_P
B_TD1_N: C58.2 T2.3(TD1_M) U4.10(MDI[3]+)
B_TD1_P: C54.2 T2.2(TD1_P) U4.11(MDI[3]-)
B_TD2_N: C57.2 T2.6(TD2_M) U4.7(MDI[2]+)
B_TD2_P: C53.2 T2.5(TD2_P) U4.8(MDI[2]-)
B_TD3_N: C52.2 T2.9(TD3_M) U4.4(MDI[1]+)
B_TD3_P: C56.2 T2.8(TD3_P) U4.5(MDI[1]-)
B_TD4_N: C55.2 T2.12(TD4_M) U4.1(MDI[0]+)
B_TD4_P: C51.2 T2.11(TD4_P) U4.2(MDI[0]-)
BEPHY_CLK: JP2.A13(LVDS7) R73.1
BEPHY_RSTN: JP2.A5(IO5) R72.1
BGE0_ENREG: R85.1 U4.38(LED2RXDLY/INTB/ENREG)
BGE0_INT_N: R83.1 U4.20(INT)
BGE0_LED0: R80.1 R81.1 R89.1 U4.34(LED0/PHYAD0)
BGE0_LED1: R75.1 R76.1 R92.1 U4.35(LED1/PHYAD1)
BGE0_LED2: R100.1 R101.1 U4.32(CLK125/LED2_RXDLY)
BGE0_PME: R87.1 R88.1 U4.33(PME)
BGE0_RXCLK: R64.2 U4.19(RXC)
BGE0_RXCTL: R65.2 R93.1 U4.13(RXCTL)
BGE0_RXD0: R66.2 R96.1 R98.1 U4.14(RXD0/SELRGV)
BGE0_RXD1: R67.2 R102.1 R103.1 U4.16(RXD1/TXDLY)
BGE0_RXD2: R68.2 R105.1 R107.1 U4.17(RXD2/AN0)
BGE0_RXD3: R70.2 R108.1 R109.1 U4.18(RXD3/AN1)
BMAC_MDC: C66.2 R90.1 R97.2 U4.30(MDC)
BMAC_MDIO: C67.2 R91.1 R99.2 U4.31(MDIO)
BPHY105: B5.1 C42.1 C43.1 C44.1 U4.3(AVDD10_1) U4.9(AVDD10_2) U4.40(AVDD10_3)
BRGMII_RXCK: JP2.C11(LVDSL5) R64.1
BRGMII_RXD0: JP2.C7(LVDSL1) R66.1
BRGMII_RXD1: JP2.C8(LVDSL2) R67.1
BRGMII_RXD2: JP2.C9(LVDSL3) R68.1
BRGMII_RXD3: JP2.C10(LVDSL4) R70.1
BRGMII_RXDV: JP2.C12(LVDSL6) R65.1
BRGMII_TXCKOUT: JP2.A11(LVDS5) U4.22(TXC)
BRGMII_TXD0: JP2.A7(LVDS1) U4.23(TXD0)
BRGMII_TXD1: JP2.A8(LVDS2) U4.24(TXD1)
BRGMII_TXD2: JP2.A9(LVDS3) U4.25(TXD2)
BRGMII_TXD3: JP2.A10(LVDS4) U4.26(TXD3)
BRGMII_TXEN: JP2.A12(LVDS6) U4.27(TXCTL)
BUART1_RXD: R112.2(B) R201.1(A) R202.1(A) ; port BUART1_RXD
BUART1_TXD: R114.2(B) R200.1(A) R203.1(A) ; port BUART1_TXD
NetB4_1: B4.1 C35.1 C36.1 C37.1 U4.44(VDDREG_2) U4.45(VDDREG_1)
NetB5_2: B5.2 C45.1 C46.1 C47.1 L2.1 U4.28(DVDD10_2) U4.36(DVDD10_1)
NetC59_1: C59.1 T2.1(TCT1) T2.4(TCT2) T2.7(TCT3) T2.10(TCT4)
NetC60_1: C60.1 R61.2 R62.2 R63.2 R69.2
NetC61_2: C61.2 R71.2 R72.2 U4.29(PHYRSTB)
NetJ3_9: R74.2 R75.2 ; port BY+
NetJ3_10: R76.2 R78.2 ; port BY-
NetJ3_11: R79.2 R80.2 ; port BG+
NetJ3_12: R81.2 R82.2 ; port BG-
NetJ3_21: R110.2 R119.2 ; port B_PWR_EN
NetJP2_A1: JP2.A1(IO1) R112.1(A)
NetJP2_A2: JP2.A2(IO2) R114.1(A)
NetJP2_B1: JP2.B1(+12V) JP2.B2(+12V) JP2.B3(+12V) JP2.B4(+12V) LED2.A(ANODE) U6.5(D) U6.6(D) U6.7(D) U6.8(D) U6.9(D)
NetJP2_C1: JP2.C1(IO6) R303.1 R314.1
NetJP2_C2: JP2.C2(IO7) R304.1 R313.1
NetJP2_C3: JP2.C3(IO8) R305.1 R312.1
NetL2_2: L2.2 U4.48(REGOUT)
NetLED2_K: LED2.K(CATHODE) R118.2
NetQ6_1: Q6.1(GATE) R95.2 R104.1
NetQ8_1: Q8.1(BASE) R110.1 R111.2
NetQ8_3: Q8.3(COLLECTOR) R104.2
NetQ10_1: Q10.1(BASE) R119.1 R120.2
NetQ10_3: Q10.3(COLLECTOR) R117.1
NetR61_1: R61.1 T2.15(MCT4)
NetR62_1: R62.1 T2.18(MCT3)
NetR63_1: R63.1 T2.21(MCT2)
NetR69_1: R69.1 T2.24(MCT1)
NetR73_2: R73.2 U4.42(CKXTAL1)
NetR77_2: R77.2 U4.39(ENREG/RSET)
NetR113_1: R113.1 R117.2 U6.4(G)
NetTP2_1: TP2.1(TP) U4.46(RSET/CLK125)

Not connected (* = marked no-connect by the designer): JP2 A14(LVDS8) A15(LVDS9) A16(LVDS10) B5(NC) B6(NC) C4(IO9) C5(IO10) C13(LVDSL7) C14(LVDSL8) C15(LVDSL9) C16(LVDSL10); U4 12(NC) 43(CKXTAL2)

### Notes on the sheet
- (Place
  these caps
  close to RJ45
  connector
  for EMI)
- MATCH ALL LENGTHS
  END TO END
  Z0 = 100 OHMS +/-10 OHMS
  NO STUBS
- MATCH ALL LENGTHS
  END TO END
  Z0 = 50 OHMS +/-10 OHMS
  NO STUBS
- GE0 Config
- 1=Wake On Lan Disable
- ADDR0
- ADDR1
- 1 = Enable switching regulator
- Pullup for Power Mgmt Enabled
  (active low signal)
- ADDR2
- TXDLY
- SET PHY ADDR:001
- Pull up for 3.3V
- add 2ns delay to RXC/TXC for RXD/TXD latching or not
- AN0
- RXDLY
- Enable Auto Negotiation
- SET:11
- AN1

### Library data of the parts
B4-B6 L2 = CHOKE TORROID_0
C35-C67 C301 = CAP NP
C68 = CAP POL
LED2 = LED_3
Q6 = MOSFET P_0
Q8 Q10 = 2N3904
R61-R83 R85 R87-R93 R96-R103 R105 R107-R109 R113 R117-R120 R303-R305 R312-R314 = R_0
R84 R86 R95 R104 R110 R111 = R
R112 R114 R200-R203 = R_1_Dup1: as R172 on sheet P05 PHY 3
T2 = PULSE H5007_0
U4 = RTL8211D_0
U5 = AS1117-X_1

## Sheet P03 PHY 1.SchDoc
size 420 x 297 mm
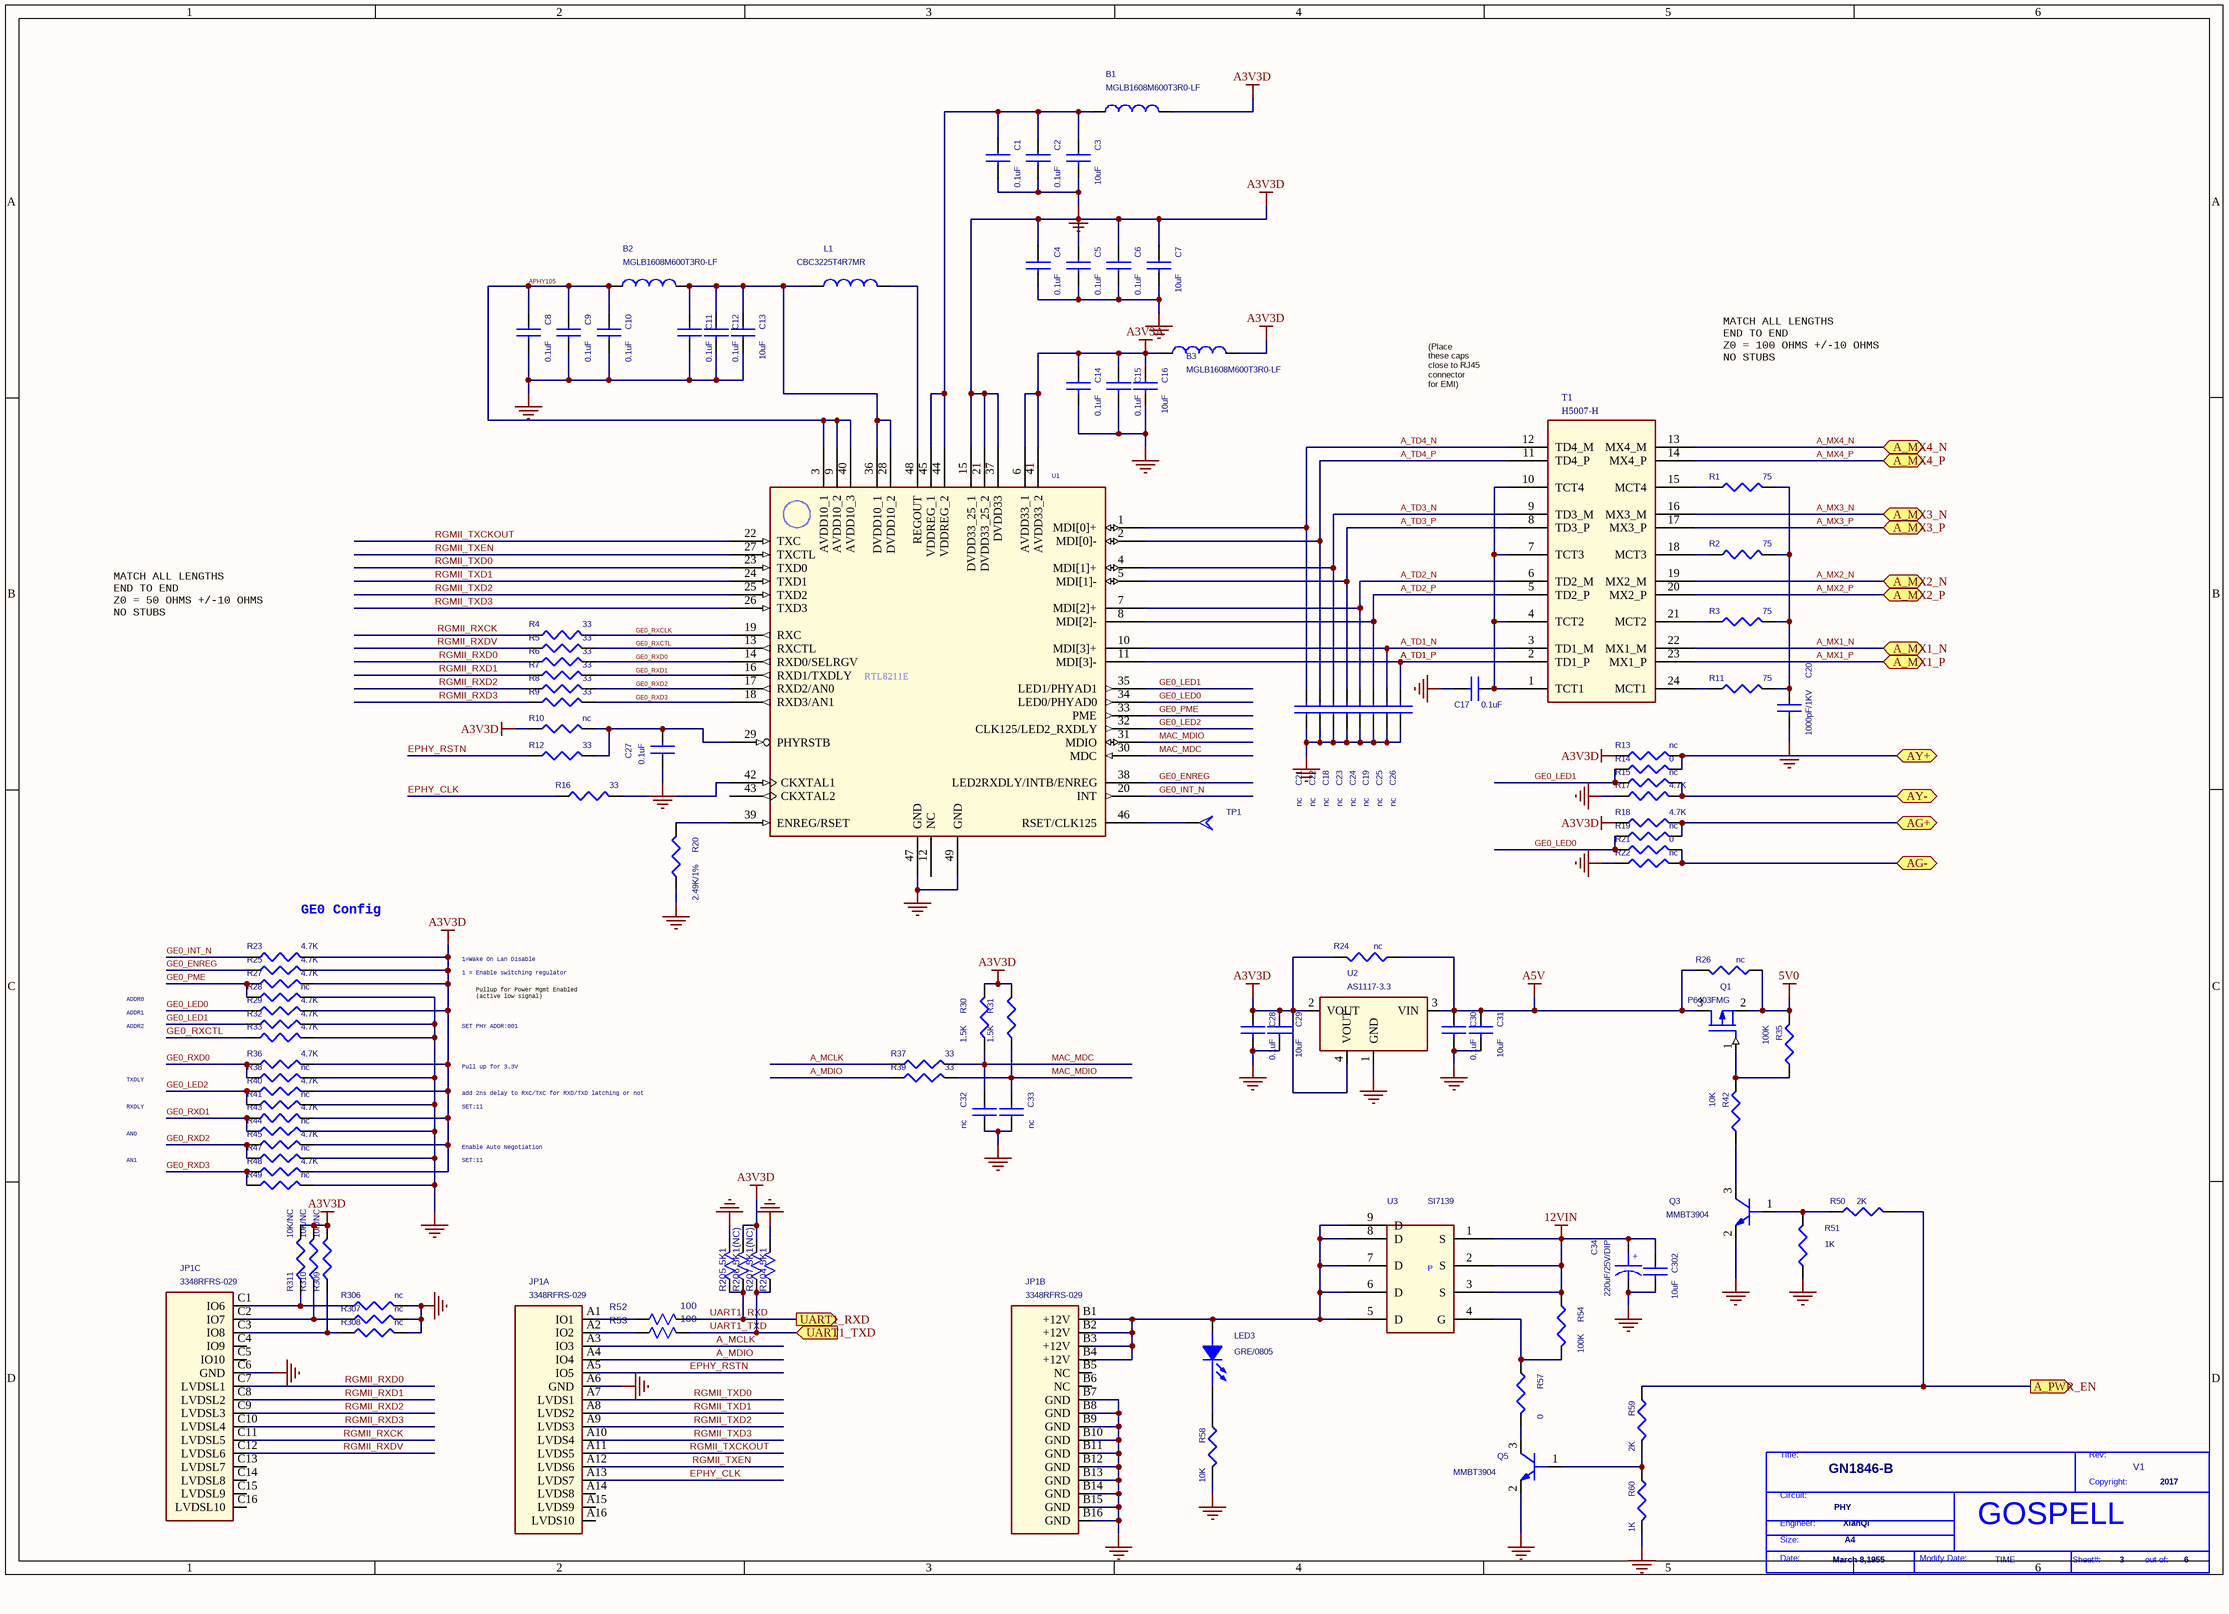
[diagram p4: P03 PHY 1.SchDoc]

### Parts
(Parts that share a designator on the sheet are numbered #1, #2 ... from top to bottom, then left to right.)
*#5  Page Modify Date: TIME  Engineer: XianQi  Copyright: 2017  Title: GN1846-B  RevCode: V1  Page Size: A4  Page Create Date: March 8,1955  Page Number: 3  Page Count: 6  Doc: PHY  (hidden comment: GOSPELL)  (graphical)
B1  MGLB1608M600T3R0-LF  [L0603]
B2  MGLB1608M600T3R0-LF  [L0603]
B3  MGLB1608M600T3R0-LF  [L0603]
C1  0.1uF  [0402C]
C2  0.1uF  [0402C]
C3  10uF  [C0603]
C4  0.1uF  [0402C]
C5  0.1uF  [0402C]
C6  0.1uF  [0402C]
C7  10uF  [C0603]
C8  0.1uF  [0402C]
C9  0.1uF  [0402C]
C10  0.1uF  [0402C]
C11  0.1uF  [0402C]
C12  0.1uF  [0402C]
C13  10uF  [C0603]
C14  0.1uF  [0402C]
C15  0.1uF  [0402C]
C16  10uF  [C0603]
C17  0.1uF  [0402C]
C18  nc  [0402C]
C19  nc  [0402C]
C20  1000pF/1KV  [C1206]
C21  nc  [0402C]
C22  nc  [0402C]
C23  nc  [0402C]
C24  nc  [0402C]
C25  nc  [0402C]
C26  nc  [0402C]
C27  0.1uF  [0402C]
C28  0.1uF  [0402C]
C29  10uF  [C0603]
C30  0.1uF  [0402C]
C31  10uF  [C0603]
C32  nc  [0402C]
C33  nc  [0402C]
C34  220uF/25V/DIP  [CE8X3.5]
C302  10uF  [c1206]
JP1  3348RFRS-029  [3348RFRS-029]  (parts A,B,C of 3)
L1  CBC3225T4R7MR  [FB0805]
LED3  GRE/0805  [LED0805]
Q1  P6403FMG  [SOT23]
Q3  MMBT3904  [SOT23]
Q5  MMBT3904  [SOT23]
R1  75  [0402R]
R2  75  [0402R]
R3  75  [0402R]
R4  33  [0402R]
R5  33  [0402R]
R6  33  [0402R]
R7  33  [0402R]
R8  33  [0402R]
R9  33  [0402R]
R10  nc  [0402R]
R11  75  [0402R]
R12  33  [0402R]
R13  nc  [0402R]
R14  0  [0402R]
R15  nc  [0402R]
R16  33  [0402R]
R17  4.7K  [0402R]
R18  4.7K  [0402R]
R19  nc  [0402R]
R20  2.49K/1%  [0402R]
R21  0  [0402R]
R22  nc  [0402R]
R23  4.7K  [0402R]
R24  nc  [R0603]
R25  4.7K  [0402R]
R26  nc  [R0603]
R27  4.7K  [0402R]
R28  nc  [0402R]
R29  4.7K  [0402R]
R30  1.5K  [0402R]
R31  1.5K  [0402R]
R32  4.7K  [0402R]
R33  4.7K  [0402R]
R35  100K  [0402R]
R36  4.7K  [0402R]
R37  33  [0402R]
R38  nc  [0402R]
R39  33  [0402R]
R40  4.7K  [0402R]
R41  nc  [0402R]
R42  10K  [0402R]
R43  4.7K  [0402R]
R44  nc  [0402R]
R45  4.7K  [0402R]
R47  nc  [0402R]
R48  4.7K  [0402R]
R49  nc  [0402R]
R50  2K  [0402R]
R51  1K  [0402R]
R52  100  [0402R]
R53  100  [0402R]
R54  100K  [R0603]
R57  0  [0402R]
R58  10K  [0402R]
R59  2K  [0402R]
R60  1K  [0402R]
R204  5K1  [0402R]
R205  5K1  [0402R]
R206  5K1(NC)  [0402R]
R207  5K1(NC)  [0402R]
R306  nc  [0402R]
R307  nc  [0402R]
R308  nc  [0402R]
R309  10K/NC  [0402R]
R310  10K/NC  [0402R]
R311  10K/NC  [0402R]
T1  H5007-H  [H5007-H]
TP1  T POINT A  [TP_G]  (value not drawn)
U1  RTL8211D  [QFN-48P-RTL8211]  (value not drawn)
U2  AS1117-3.3  [SOT223]
U3  SI7139  [PowerPAKSO8]

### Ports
A_MX1_N (bidir), A_MX1_P (bidir), A_MX2_N (bidir), A_MX2_P (bidir), A_MX3_N (bidir), A_MX3_P (bidir), A_MX4_N (bidir), A_MX4_P (bidir), A_PWR_EN (out), AG+ (bidir), AG- (bidir), AY+ (bidir), AY- (bidir), UART1_RXD (out), UART1_TXD (in)

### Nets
5V0: Q1.2(SOURCE) R26.2 R35.1
12VIN: C34.1 C302.1 R54.2 U3.1(S) U3.2(S) U3.3(S)
A3V3A: B3.1 C14.1 C15.1 C16.1 U1.6(AVDD33_1) U1.41(AVDD33_2)
A3V3D: B1.2 B3.2 C4.1 C5.1 C6.1 C7.1 C28.1 C29.1 R10.1 R13.1 R18.1 R23.2 R24.1 R25.2 R27.2 R29.2 R30.2 R31.2 R36.2 R40.2 R43.2 R45.2 R48.2 R206.2(B) R207.2(B) R309.2 R310.2 R311.2 U1.15(DVDD33_25_1) U1.21(DVDD33_25_2) U1.37(DVDD33) U2.2(VOUT) U2.4(VOUT)
A5V: C30.1 C31.1 Q1.3(DRAIN) R24.2 R26.1 U2.3(VIN)
GND: C1.2 C2.2 C3.2 C4.2 C5.2 C6.2 C7.2 C8.2 C9.2 C10.2 C11.2 C12.2 C13.2 C14.2 C15.2 C16.2 C17.2 C18.1 C19.1 C20.2 C21.1 C22.1 C23.1 C24.1 C25.1 C26.1 C27.1 C28.2 C29.2 C30.2 C31.2 C32.1 C33.1 C34.2 C302.2 JP1.A6(GND) JP1.B7(GND) JP1.B8(GND) JP1.B9(GND) JP1.B10(GND) JP1.B11(GND) JP1.B12(GND) JP1.B13(GND) JP1.B14(GND) JP1.B15(GND) JP1.B16(GND) JP1.C6(GND) Q3.2(EMITTER) Q5.2(EMITTER) R17.1 R20.1 R22.1 R28.2 R32.2 R33.2 R38.2 R41.2 R44.2 R47.2 R49.2 R51.1 R58.1 R60.1 R204.2(B) R205.2(B) R306.2 R307.2 R308.2 U1.47(GND) U1.49(GND) U2.1(GND)
A_MCLK: JP1.A3(IO3) R37.1
A_MDIO: JP1.A4(IO4) R39.1
A_MX1_N: T1.22(MX1_M) ; port A_MX1_N
A_MX1_P: T1.23(MX1_P) ; port A_MX1_P
A_MX2_N: T1.19(MX2_M) ; port A_MX2_N
A_MX2_P: T1.20(MX2_P) ; port A_MX2_P
A_MX3_N: T1.16(MX3_M) ; port A_MX3_N
A_MX3_P: T1.17(MX3_P) ; port A_MX3_P
A_MX4_N: T1.13(MX4_M) ; port A_MX4_N
A_MX4_P: T1.14(MX4_P) ; port A_MX4_P
A_TD1_N: C25.2 T1.3(TD1_M) U1.10(MDI[3]+)
A_TD1_P: C26.2 T1.2(TD1_P) U1.11(MDI[3]-)
A_TD2_N: C24.2 T1.6(TD2_M) U1.7(MDI[2]+)
A_TD2_P: C19.2 T1.5(TD2_P) U1.8(MDI[2]-)
A_TD3_N: C18.2 T1.9(TD3_M) U1.4(MDI[1]+)
A_TD3_P: C23.2 T1.8(TD3_P) U1.5(MDI[1]-)
A_TD4_N: C21.2 T1.12(TD4_M) U1.1(MDI[0]+)
A_TD4_P: C22.2 T1.11(TD4_P) U1.2(MDI[0]-)
APHY105: B2.1 C8.1 C9.1 C10.1 U1.3(AVDD10_1) U1.9(AVDD10_2) U1.40(AVDD10_3)
EPHY_CLK: JP1.A13(LVDS7) R16.1
EPHY_RSTN: JP1.A5(IO5) R12.1
GE0_ENREG: R25.1 U1.38(LED2RXDLY/INTB/ENREG)
GE0_INT_N: R23.1 U1.20(INT)
GE0_LED0: R19.1 R21.1 R29.1 U1.34(LED0/PHYAD0)
GE0_LED1: R14.1 R15.1 R32.1 U1.35(LED1/PHYAD1)
GE0_LED2: R40.1 R41.1 U1.32(CLK125/LED2_RXDLY)
GE0_PME: R27.1 R28.1 U1.33(PME)
GE0_RXCLK: R4.2 U1.19(RXC)
GE0_RXCTL: R5.2 R33.1 U1.13(RXCTL)
GE0_RXD0: R6.2 R36.1 R38.1 U1.14(RXD0/SELRGV)
GE0_RXD1: R7.2 R43.1 R44.1 U1.16(RXD1/TXDLY)
GE0_RXD2: R8.2 R45.1 R47.1 U1.17(RXD2/AN0)
GE0_RXD3: R9.2 R48.1 R49.1 U1.18(RXD3/AN1)
MAC_MDC: C32.2 R30.1 R37.2 U1.30(MDC)
MAC_MDIO: C33.2 R31.1 R39.2 U1.31(MDIO)
RGMII_RXCK: JP1.C11(LVDSL5) R4.1
RGMII_RXD0: JP1.C7(LVDSL1) R6.1
RGMII_RXD1: JP1.C8(LVDSL2) R7.1
RGMII_RXD2: JP1.C9(LVDSL3) R8.1
RGMII_RXD3: JP1.C10(LVDSL4) R9.1
RGMII_RXDV: JP1.C12(LVDSL6) R5.1
RGMII_TXCKOUT: JP1.A11(LVDS5) U1.22(TXC)
RGMII_TXD0: JP1.A7(LVDS1) U1.23(TXD0)
RGMII_TXD1: JP1.A8(LVDS2) U1.24(TXD1)
RGMII_TXD2: JP1.A9(LVDS3) U1.25(TXD2)
RGMII_TXD3: JP1.A10(LVDS4) U1.26(TXD3)
RGMII_TXEN: JP1.A12(LVDS6) U1.27(TXCTL)
UART1_RXD: R52.2(B) R205.1(A) R206.1(A) ; port UART1_RXD
UART1_TXD: R53.2(B) R204.1(A) R207.1(A) ; port UART1_TXD
NetB1_1: B1.1 C1.1 C2.1 C3.1 U1.44(VDDREG_2) U1.45(VDDREG_1)
NetB2_2: B2.2 C11.1 C12.1 C13.1 L1.1 U1.28(DVDD10_2) U1.36(DVDD10_1)
NetC17_1: C17.1 T1.1(TCT1) T1.4(TCT2) T1.7(TCT3) T1.10(TCT4)
NetC20_1: C20.1 R1.2 R2.2 R3.2 R11.2
NetC27_2: C27.2 R10.2 R12.2 U1.29(PHYRSTB)
NetJ3_24: R50.2 R59.2 ; port A_PWR_EN
NetJ4_9: R13.2 R14.2 ; port AY+
NetJ4_10: R15.2 R17.2 ; port AY-
NetJ4_11: R18.2 R19.2 ; port AG+
NetJ4_12: R21.2 R22.2 ; port AG-
NetJP1_A1: JP1.A1(IO1) R52.1(A)
NetJP1_A2: JP1.A2(IO2) R53.1(A)
NetJP1_B1: JP1.B1(+12V) JP1.B2(+12V) JP1.B3(+12V) JP1.B4(+12V) LED3.A(ANODE) U3.5(D) U3.6(D) U3.7(D) U3.8(D) U3.9(D)
NetJP1_C1: JP1.C1(IO6) R306.1 R311.1
NetJP1_C2: JP1.C2(IO7) R307.1 R310.1
NetJP1_C3: JP1.C3(IO8) R308.1 R309.1
NetL1_2: L1.2 U1.48(REGOUT)
NetLED3_K: LED3.K(CATHODE) R58.2
NetQ1_1: Q1.1(GATE) R35.2 R42.1
NetQ3_1: Q3.1(BASE) R50.1 R51.2
NetQ3_3: Q3.3(COLLECTOR) R42.2
NetQ5_1: Q5.1(BASE) R59.1 R60.2
NetQ5_3: Q5.3(COLLECTOR) R57.1
NetR1_1: R1.1 T1.15(MCT4)
NetR2_1: R2.1 T1.18(MCT3)
NetR3_1: R3.1 T1.21(MCT2)
NetR11_1: R11.1 T1.24(MCT1)
NetR16_2: R16.2 U1.42(CKXTAL1)
NetR20_2: R20.2 U1.39(ENREG/RSET)
NetR54_1: R54.1 R57.2 U3.4(G)
NetTP1_1: TP1.1(TP) U1.46(RSET/CLK125)

Not connected (* = marked no-connect by the designer): JP1 A14(LVDS8) A15(LVDS9) A16(LVDS10) B5(NC) B6(NC) C4(IO9) C5(IO10) C13(LVDSL7) C14(LVDSL8) C15(LVDSL9) C16(LVDSL10); U1 12(NC) 43(CKXTAL2)

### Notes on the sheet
- (Place
  these caps
  close to RJ45
  connector
  for EMI)
- MATCH ALL LENGTHS
  END TO END
  Z0 = 100 OHMS +/-10 OHMS
  NO STUBS
- MATCH ALL LENGTHS
  END TO END
  Z0 = 50 OHMS +/-10 OHMS
  NO STUBS
- GE0 Config
- 1 = Enable switching regulator
- 1=Wake On Lan Disable
- Pullup for Power Mgmt Enabled
  (active low signal)
- ADDR0
- ADDR1
- ADDR2
- SET PHY ADDR:001
- Pull up for 3.3V
- TXDLY
- RXDLY
- add 2ns delay to RXC/TXC for RXD/TXD latching or not
- SET:11
- AN0
- AN1
- Enable Auto Negotiation

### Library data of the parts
B1-B3 L1 = CHOKE TORROID_0
C1-C33 C302 = CAP NP
C34 = CAP POL
LED3 = LED_4
Q1 = MOSFET P_0
Q3 Q5 = 2N3904
R1-R23 R25 R27-R33 R36-R41 R43-R45 R47-R49 R54 R57-R60 R306-R311 = R_0
R24 R26 R35 R42 R50 R51 = R
R52 R53 R204-R207 = R_1_Dup1: as R172 on sheet P05 PHY 3
T1 = PULSE H5007_0
U1 = RTL8211D_0
U2 = AS1117-X_1

## Sheet P01 Note & Title.SchDoc
size 297 x 209 mm
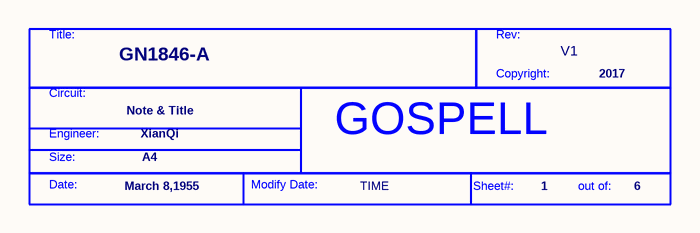
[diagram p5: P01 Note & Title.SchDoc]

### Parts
(Parts that share a designator on the sheet are numbered #1, #2 ... from top to bottom, then left to right.)
*#6  Page Modify Date: TIME  Engineer: XianQi  Copyright: 2017  Title: GN1846-A  RevCode: V1  Page Size: A4  Page Create Date: March 8,1955  Page Number: 1  Page Count: 6  Doc: Note & Title  (hidden comment: GOSPELL)  (graphical)

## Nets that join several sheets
5V0: P05 PHY 3 (Q11.2 R146.2 R155.1), P06 CONNECT & LED (J2.9 J2.10 J2.11 J2.12), P04 PHY 2 (Q6.2 R86.2 R95.1), P03 PHY 1 (Q1.2 R26.2 R35.1)
12VIN: P05 PHY 3 (6 pins), P06 CONNECT & LED (8 pins), P04 PHY 2 (6 pins), P03 PHY 1 (6 pins)
GND: P02 Block (64 pins), P05 PHY 3 (71 pins), P06 CONNECT & LED (15 pins), P04 PHY 2 (71 pins), P03 PHY 1 (71 pins)
A_MX1_N: P06 CONNECT & LED (J4.7), P03 PHY 1 (T1.22)
A_MX1_P: P06 CONNECT & LED (J4.8), P03 PHY 1 (T1.23)
A_MX2_N: P06 CONNECT & LED (J4.5), P03 PHY 1 (T1.19)
A_MX2_P: P06 CONNECT & LED (J4.6), P03 PHY 1 (T1.20)
A_MX3_N: P06 CONNECT & LED (J4.1), P03 PHY 1 (T1.16)
A_MX3_P: P06 CONNECT & LED (J4.2), P03 PHY 1 (T1.17)
A_MX4_N: P06 CONNECT & LED (J4.3), P03 PHY 1 (T1.13)
A_MX4_P: P06 CONNECT & LED (J4.4), P03 PHY 1 (T1.14)
B_MX1_N: P06 CONNECT & LED (J3.8), P04 PHY 2 (T2.22)
B_MX1_P: P06 CONNECT & LED (J3.7), P04 PHY 2 (T2.23)
B_MX2_N: P06 CONNECT & LED (J3.6), P04 PHY 2 (T2.19)
B_MX2_P: P06 CONNECT & LED (J3.5), P04 PHY 2 (T2.20)
B_MX3_N: P06 CONNECT & LED (J3.2), P04 PHY 2 (T2.16)
B_MX3_P: P06 CONNECT & LED (J3.1), P04 PHY 2 (T2.17)
B_MX4_N: P06 CONNECT & LED (J3.4), P04 PHY 2 (T2.13)
B_MX4_P: P06 CONNECT & LED (J3.3), P04 PHY 2 (T2.14)
BUART1_RXD: P06 CONNECT & LED (J3.23), P04 PHY 2 (R112.2 R201.1 R202.1)
BUART1_TXD: P06 CONNECT & LED (J3.22), P04 PHY 2 (R114.2 R200.1 R203.1)
C_MX1_N: P05 PHY 3 (T3.22), P06 CONNECT & LED (J4.24)
C_MX1_P: P05 PHY 3 (T3.23), P06 CONNECT & LED (J4.23)
C_MX2_N: P05 PHY 3 (T3.19), P06 CONNECT & LED (J4.22)
C_MX2_P: P05 PHY 3 (T3.20), P06 CONNECT & LED (J4.21)
C_MX3_N: P05 PHY 3 (T3.16), P06 CONNECT & LED (J4.20)
C_MX3_P: P05 PHY 3 (T3.17), P06 CONNECT & LED (J4.19)
C_MX4_N: P05 PHY 3 (T3.13), P06 CONNECT & LED (J4.26)
C_MX4_P: P05 PHY 3 (T3.14), P06 CONNECT & LED (J4.25)
CUART1_RXD: P05 PHY 3 (R172.2 R208.1 R210.1), P06 CONNECT & LED (J3.19)
CUART1_TXD: P05 PHY 3 (R173.2 R209.1 R211.1), P06 CONNECT & LED (J3.20)
NetJ3_9: P06 CONNECT & LED (J3.9), P04 PHY 2 (R74.2 R75.2)
NetJ3_10: P06 CONNECT & LED (J3.10), P04 PHY 2 (R76.2 R78.2)
NetJ3_11: P06 CONNECT & LED (J3.11), P04 PHY 2 (R79.2 R80.2)
NetJ3_12: P06 CONNECT & LED (J3.12), P04 PHY 2 (R81.2 R82.2)
NetJ3_18: P05 PHY 3 (R170.2 R179.2), P06 CONNECT & LED (J3.18)
NetJ3_21: P06 CONNECT & LED (J3.21), P04 PHY 2 (R110.2 R119.2)
NetJ3_24: P06 CONNECT & LED (J3.24), P03 PHY 1 (R50.2 R59.2)
NetJ4_9: P06 CONNECT & LED (J4.9), P03 PHY 1 (R13.2 R14.2)
NetJ4_10: P06 CONNECT & LED (J4.10), P03 PHY 1 (R15.2 R17.2)
NetJ4_11: P06 CONNECT & LED (J4.11), P03 PHY 1 (R18.2 R19.2)
NetJ4_12: P06 CONNECT & LED (J4.12), P03 PHY 1 (R21.2 R22.2)
NetJ4_15: P05 PHY 3 (R134.2 R135.2), P06 CONNECT & LED (J4.15)
NetJ4_16: P05 PHY 3 (R136.2 R138.2), P06 CONNECT & LED (J4.16)
NetJ4_17: P05 PHY 3 (R139.2 R140.2), P06 CONNECT & LED (J4.17)
NetJ4_18: P05 PHY 3 (R141.2 R142.2), P06 CONNECT & LED (J4.18)
UART1_RXD: P06 CONNECT & LED (J3.26), P03 PHY 1 (R52.2 R205.1 R206.1)
UART1_TXD: P06 CONNECT & LED (J3.25), P03 PHY 1 (R53.2 R204.1 R207.1)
